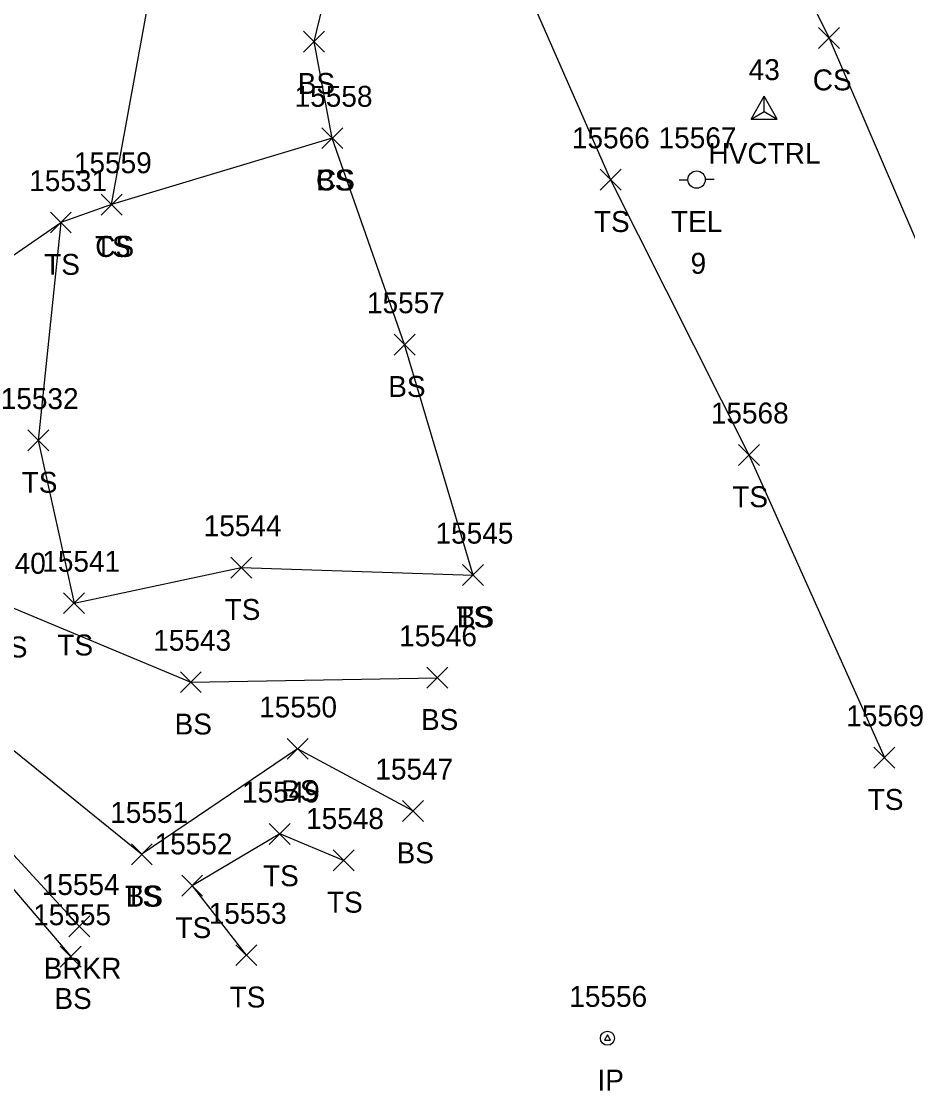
# Model space of a CAD drawing. Extents: x 1606530 to 1613020, y 784959 to 789666.
# Drawn here: x 1609182 to 1609266.7, y 788233.3 to 788335.5 of the extents above; entities that cross this region are included whole.
import ezdxf

# ---------------------------------------------------------------- set-up
doc = ezdxf.new("R2010")
doc.units = 0
for name, color, linetype in [('C_A', 7, 'Continuous'), ('C_I', 7, 'Continuous'), ('CPSM', 7, 'Continuous'), ('L_A', 7, 'Continuous'), ('L_I', 7, 'Continuous'), ('L_TIC', 7, 'Continuous'), ('LAWE', 7, 'Continuous'), ('LELB', 7, 'Continuous'), ('M_A', 7, 'Continuous'), ('M_I', 7, 'Continuous'), ('MPIR', 7, 'Continuous'), ('U_A', 7, 'Continuous'), ('U_C', 7, 'Continuous'), ('U_I', 7, 'Continuous'), ('UP', 7, 'Continuous')]:
    doc.layers.add(name, color=color, linetype=linetype)

msp = doc.modelspace()

# ---------------------------------------------------------------- linework, layer by layer
at = {"layer": 'CPSM'}
for p, q in [((1609251.73, 788326.13), (1609252.98, 788328.3)), ((1609254.23, 788326.13), (1609252.98, 788328.3)), ((1609252.98, 788326.85), (1609252.98, 788328.3)), ((1609251.73, 788326.13), (1609252.98, 788326.85)), ((1609252.98, 788326.85), (1609252.98, 788326.85)), ((1609252.98, 788326.85), (1609254.23, 788326.13)), ((1609251.73, 788326.13), (1609254.23, 788326.13))]:
    msp.add_line(p, q, dxfattribs=at)
at = {"layer": 'L_TIC'}
for points in [[(1609208.98, 788332.53), (1609210.98, 788334.53)], [(1609210.98, 788332.53), (1609208.98, 788334.53)], [(1609258.19, 788332.87), (1609260.19, 788334.87)], [(1609260.19, 788332.87), (1609258.19, 788334.87)], [(1609210.72, 788323.3), (1609212.72, 788325.3)], [(1609212.72, 788323.3), (1609210.72, 788325.3)], [(1609210.72, 788323.3), (1609212.72, 788325.3)], [(1609212.72, 788323.3), (1609210.72, 788325.3)], [(1609237.31, 788319.33), (1609239.31, 788321.33)], [(1609239.31, 788319.33), (1609237.31, 788321.33)], [(1609189.64, 788316.95), (1609191.64, 788318.95)], [(1609191.64, 788316.95), (1609189.64, 788318.95)], [(1609189.64, 788316.95), (1609191.64, 788318.95)], [(1609191.64, 788316.95), (1609189.64, 788318.95)], [(1609184.79, 788315.24), (1609186.79, 788317.24)], [(1609186.79, 788315.24), (1609184.79, 788317.24)], [(1609184.79, 788315.24), (1609186.79, 788317.24)], [(1609186.79, 788315.24), (1609184.79, 788317.24)], [(1609217.63, 788303.57), (1609219.63, 788305.57)], [(1609219.63, 788303.57), (1609217.63, 788305.57)], [(1609182.64, 788294.41), (1609184.64, 788296.41)], [(1609184.64, 788294.41), (1609182.64, 788296.41)], [(1609250.53, 788293.03), (1609252.53, 788295.03)], [(1609252.53, 788293.03), (1609250.53, 788295.03)], [(1609202.03, 788282.26), (1609204.03, 788284.26)], [(1609204.03, 788282.26), (1609202.03, 788284.26)], [(1609224.18, 788281.55), (1609226.18, 788283.55)], [(1609226.18, 788281.55), (1609224.18, 788283.55)], [(1609224.18, 788281.55), (1609226.18, 788283.55)], [(1609226.18, 788281.55), (1609224.18, 788283.55)], [(1609186.05, 788278.86), (1609188.05, 788280.86)], [(1609188.05, 788278.86), (1609186.05, 788280.86)], [(1609220.75, 788271.74), (1609222.75, 788273.74)], [(1609222.75, 788271.74), (1609220.75, 788273.74)], [(1609197.21, 788271.31), (1609199.21, 788273.31)], [(1609199.21, 788271.31), (1609197.21, 788273.31)], [(1609207.41, 788264.94), (1609209.41, 788266.94)], [(1609209.41, 788264.94), (1609207.41, 788266.94)], [(1609263.47, 788264.1), (1609265.47, 788266.1)], [(1609265.47, 788264.1), (1609263.47, 788266.1)], [(1609218.43, 788259), (1609220.43, 788261)], [(1609220.43, 788259), (1609218.43, 788261)], [(1609205.7, 788256.81), (1609207.7, 788258.81)], [(1609207.7, 788256.81), (1609205.7, 788258.81)], [(1609192.53, 788254.86), (1609194.53, 788256.86)], [(1609194.53, 788254.86), (1609192.53, 788256.86)], [(1609192.53, 788254.86), (1609194.53, 788256.86)], [(1609194.53, 788254.86), (1609192.53, 788256.86)], [(1609211.81, 788254.28), (1609213.81, 788256.28)], [(1609213.81, 788254.28), (1609211.81, 788256.28)], [(1609197.34, 788251.85), (1609199.34, 788253.85)], [(1609199.34, 788251.85), (1609197.34, 788253.85)], [(1609186.56, 788247.97), (1609188.56, 788249.97)], [(1609188.56, 788247.97), (1609186.56, 788249.97)], [(1609202.51, 788245.22), (1609204.51, 788247.22)], [(1609204.51, 788245.22), (1609202.51, 788247.22)], [(1609185.74, 788245.08), (1609187.74, 788247.08)], [(1609187.74, 788245.08), (1609185.74, 788247.08)]]:
    msp.add_lwpolyline(points, dxfattribs=at)
at = {"layer": 'LAWE'}
msp.add_lwpolyline([(1609171.99, 788355.54), (1609163.51, 788343.02), (1609160.55, 788326.15), (1609159.75, 788312.64), (1609162.58, 788294.54), (1609165.68, 788272.74), (1609187.56, 788248.97)], dxfattribs=at)
at = {"layer": 'LELB'}
for points in [[(1609222.59, 788380.4), (1609229.47, 788383.53), (1609244.73, 788362.88), (1609259.19, 788333.87), (1609270.6, 788307.32)], [(1609181.94, 788380.54), (1609177.62, 788370.24), (1609175.84, 788366.16), (1609170.24, 788364.55), (1609169.24, 788358.22), (1609162.45, 788343.09), (1609158.86, 788325.59), (1609159.24, 788313.17), (1609161.54, 788294.45), (1609164.83, 788271.75), (1609186.74, 788246.08)], [(1609190.64, 788317.95), (1609196.09, 788347.84), (1609212.86, 788370.15), (1609222.59, 788380.4), (1609223.66, 788353.69), (1609238.31, 788320.33), (1609251.53, 788294.03), (1609264.47, 788265.1)], [(1609225.18, 788282.55), (1609218.63, 788304.57), (1609211.72, 788324.3), (1609209.98, 788333.53), (1609213.48, 788347.88), (1609212.86, 788370.15)], [(1609164.85, 788341.25), (1609162.76, 788324.69), (1609162.61, 788310.85), (1609162.36, 788303.22), (1609165.18, 788294.05), (1609169.03, 788275.69), (1609193.53, 788255.86)], [(1609211.72, 788324.3), (1609190.64, 788317.95)], [(1609190.64, 788317.95), (1609185.79, 788316.24)], [(1609162.36, 788303.22), (1609176.11, 788309.57), (1609185.79, 788316.24)], [(1609185.79, 788316.24), (1609183.64, 788295.41), (1609187.05, 788279.86), (1609203.03, 788283.26), (1609225.18, 788282.55)], [(1609176.11, 788309.57), (1609176.96, 788295.72), (1609180.59, 788279.67), (1609198.21, 788272.31), (1609221.75, 788272.74)], [(1609219.43, 788260), (1609208.41, 788265.94), (1609193.53, 788255.86)], [(1609212.81, 788255.28), (1609206.7, 788257.81), (1609198.34, 788252.85), (1609203.51, 788246.22)]]:
    msp.add_lwpolyline(points, dxfattribs=at)
at = {"layer": 'MPIR'}
msp.add_lwpolyline([(1609238.01, 788238.61), (1609237.72, 788238.11), (1609238.3, 788238.11)], close=True, dxfattribs=at)
msp.add_circle((1609238.01, 788238.28), 0.667, dxfattribs=at)
at = {"layer": 'UP'}
for p, q in [((1609244.87, 788320.33), (1609245.7, 788320.33)), ((1609246.53, 788320.34), (1609246.53, 788320.34)), ((1609248.2, 788320.34), (1609247.37, 788320.34)), ((1609247.37, 788320.34), (1609247.37, 788320.34)), ((1609248.2, 788320.34), (1609248.2, 788320.34))]:
    msp.add_line(p, q, dxfattribs=at)
msp.add_circle((1609246.53, 788320.34), 0.833, dxfattribs=at)

# ---------------------------------------------------------------- texts
at = {"layer": 'C_A'}
msp.add_text('HVCTRL', height=2, dxfattribs=at).set_placement((1609247.67, 788321.85))
at = {"layer": 'C_I'}
msp.add_text('43', height=2, dxfattribs=at).set_placement((1609251.51, 788329.85))
at = {"layer": 'L_A'}
for s, p in [('BS', (1609208.42, 788328.53)), ('CS', (1609257.63, 788328.87)), ('CS', (1609210.17, 788319.3)), ('BS', (1609210.17, 788319.3)), ('TS', (1609236.72, 788315.33)), ('TS', (1609189.05, 788312.95)), ('CS', (1609189.08, 788312.95)), ('TS', (1609184.2, 788311.24)), ('TS', (1609184.2, 788311.24)), ('BS', (1609217.07, 788299.57)), ('TS', (1609182.05, 788290.41)), ('TS', (1609249.94, 788289.03)), ('TS', (1609201.44, 788278.26)), ('TS', (1609223.59, 788277.55)), ('BS', (1609223.62, 788277.55)), ('TS', (1609185.46, 788274.86)), ('BS', (1609179.04, 788274.67)), ('BS', (1609220.2, 788267.74)), ('BS', (1609196.66, 788267.31)), ('BS', (1609206.85, 788260.94)), ('TS', (1609262.88, 788260.1)), ('BS', (1609217.87, 788255)), ('TS', (1609205.11, 788252.81)), ('TS', (1609191.94, 788250.86)), ('BS', (1609191.98, 788250.86)), ('TS', (1609211.22, 788250.28)), ('TS', (1609196.75, 788247.85)), ('BRKR', (1609184.15, 788243.97)), ('BS', (1609185.18, 788241.08)), ('TS', (1609201.92, 788241.22))]:
    msp.add_text(s, height=2, dxfattribs=at).set_placement(p)
at = {"layer": 'L_I'}
for s, p in [('15558', (1609208.13, 788327.3)), ('15558', (1609208.13, 788327.3)), ('15566', (1609234.62, 788323.33)), ('15559', (1609187.04, 788320.95)), ('15559', (1609187.04, 788320.95)), ('15531', (1609182.77, 788319.24)), ('15531', (1609182.77, 788319.24)), ('15557', (1609215.04, 788307.57)), ('15532', (1609180.05, 788298.41)), ('15568', (1609247.89, 788297.03)), ('15544', (1609199.44, 788286.26)), ('15545', (1609221.59, 788285.55)), ('15545', (1609221.59, 788285.55)), ('15540', (1609176.92, 788282.67)), ('15541', (1609184.02, 788282.86)), ('15543', (1609194.62, 788275.31)), ('15546', (1609218.11, 788275.74)), ('15550', (1609204.74, 788268.94)), ('15569', (1609260.83, 788268.1)), ('15547', (1609215.84, 788263)), ('15549', (1609203.1, 788260.81)), ('15551', (1609190.51, 788258.86)), ('15551', (1609190.51, 788258.86)), ('15548', (1609209.22, 788258.28)), ('15552', (1609194.75, 788255.85)), ('15554', (1609183.97, 788251.97)), ('15553', (1609199.92, 788249.22)), ('15555', (1609183.15, 788249.08))]:
    msp.add_text(s, height=2, dxfattribs=at).set_placement(p)
at = {"layer": 'M_A'}
msp.add_text('IP', height=2, dxfattribs=at).set_placement((1609237.06, 788233.28))
at = {"layer": 'M_I'}
msp.add_text('15556', height=2, dxfattribs=at).set_placement((1609234.37, 788241.28))
at = {"layer": 'U_A'}
msp.add_text('TEL', height=2, dxfattribs=at).set_placement((1609244.09, 788315.34))
at = {"layer": 'U_C'}
msp.add_text('9', height=2, dxfattribs=at).set_placement((1609245.96, 788311.34))
at = {"layer": 'U_I'}
msp.add_text('15567', height=2, dxfattribs=at).set_placement((1609242.9, 788323.34))

doc.saveas('drawing.dxf')
